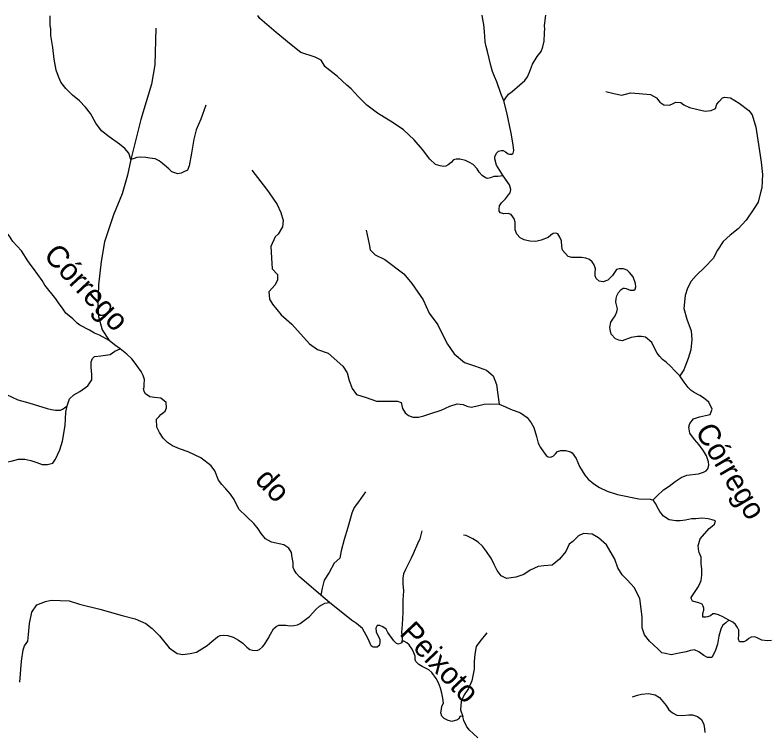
# Model space of a CAD drawing. Extents: x 436.3 to 500.4, y 8231 to 8286.4.
# Drawn here: x 461.07 to 467.97, y 8279.76 to 8286.32 of the extents above; entities that cross this region are included whole.
import ezdxf
from ezdxf.enums import TextEntityAlignment as Align

# ---------------------------------------------------------------- set-up
doc = ezdxf.new("R2010")
doc.units = 0
doc.header["$LTSCALE"] = 0.08
doc.linetypes.add('LONG_DASHED', pattern=[7.5, 6, -1.5])
doc.layers.add('61', color=7, linetype='Continuous')
doc.layers.add('7', color=7, linetype='Continuous', lineweight=25)
doc.layers.add('9', color=7, linetype='LONG_DASHED', lineweight=25)

msp = doc.modelspace()

# ---------------------------------------------------------------- linework, layer by layer
at = {"layer": '7'}
for points in [[(465.5464, 8285.5384), (465.5194, 8285.6056), (465.4833, 8285.7132), (465.4608, 8285.7625), (465.4428, 8285.8073), (465.4274, 8285.862), (465.3978, 8285.991), (465.3843, 8286.0358), (465.3752, 8286.0806), (465.3727, 8286.1274), (465.3685, 8286.1698), (465.3625, 8286.2385), (465.3536, 8286.2853), (465.3464, 8286.324)], [(465.5396, 8284.8515), (465.4782, 8284.9504), (465.463, 8285.0078), (465.463, 8285.026), (465.4781, 8285.0592), (465.4963, 8285.0773), (465.5204, 8285.0834), (465.5386, 8285.0834), (465.5598, 8285.0714), (465.5841, 8285.0533), (465.5991, 8285.0503), (465.6204, 8285.0503), (465.6322, 8285.0585), (465.6366, 8285.0854), (465.6321, 8285.1348), (465.614, 8285.2424), (465.5746, 8285.4337), (465.5464, 8285.5384)], [(467.1578, 8283.0201), (467.1083, 8283.0695), (467.0768, 8283.1055), (467.0318, 8283.1459), (467.0003, 8283.1684), (466.9733, 8283.1953), (466.9508, 8283.2268), (466.9283, 8283.2673), (466.9012, 8283.3257), (466.8427, 8283.3751), (466.8068, 8283.3795), (466.7708, 8283.3795), (466.7127, 8283.3718), (466.631, 8283.3415), (466.5977, 8283.3474), (466.5674, 8283.3595), (466.528, 8283.4018), (466.5219, 8283.4291), (466.5158, 8283.4624), (466.5248, 8283.5109), (466.543, 8283.5381), (466.5671, 8283.5684), (466.5822, 8283.6047), (466.5881, 8283.632), (466.573, 8283.6955), (466.5759, 8283.7288), (466.582, 8283.753), (466.597, 8283.7833), (466.6212, 8283.8106), (466.6394, 8283.8227), (466.6514, 8283.8228), (466.6666, 8283.8198), (466.703, 8283.8047), (466.7362, 8283.8047), (466.7484, 8283.8138), (466.7543, 8283.835), (466.7521, 8283.8652), (466.7302, 8283.9259), (466.697, 8283.9652), (466.6757, 8283.9863), (466.6424, 8283.9984), (466.6031, 8283.9983), (466.5788, 8283.9922), (466.5426, 8283.9377), (466.4972, 8283.8953), (466.4549, 8283.8801), (466.4186, 8283.8861), (466.3913, 8283.9103), (466.3822, 8283.9345), (466.3821, 8283.9677), (466.3852, 8284.001), (466.3729, 8284.0373), (466.3547, 8284.0645), (466.3305, 8284.0856), (466.2981, 8284.0982), (466.2577, 8284.1027), (466.1678, 8284.1026), (466.1364, 8284.1115), (466.0824, 8284.1698), (466.0783, 8284.2031), (466.0753, 8284.2575), (466.0601, 8284.2907), (466.0419, 8284.321), (466.0207, 8284.3269), (465.9965, 8284.3239), (465.9753, 8284.3088), (465.9512, 8284.2876), (465.8876, 8284.2633), (465.8392, 8284.2511), (465.7847, 8284.254), (465.7333, 8284.2662), (465.6969, 8284.2842), (465.6636, 8284.3175), (465.6484, 8284.3567), (465.6483, 8284.4263), (465.6392, 8284.4565), (465.627, 8284.4777), (465.6119, 8284.4988), (465.5847, 8284.5079), (465.5453, 8284.5048), (465.515, 8284.5138), (465.5029, 8284.529), (465.5029, 8284.547), (465.5069, 8284.578), (465.524, 8284.6045), (465.5602, 8284.6408), (465.5875, 8284.6772), (465.6026, 8284.6952), (465.6086, 8284.7255), (465.5964, 8284.7693), (465.5396, 8284.8515)], [(461.9308, 8283.3419), (461.8418, 8283.3924), (461.7968, 8283.4105), (461.7518, 8283.4375), (461.6619, 8283.4826), (461.6394, 8283.5006), (461.5989, 8283.5411), (461.5359, 8283.5951), (461.5044, 8283.6401), (461.4729, 8283.6806), (461.4415, 8283.726), (461.3424, 8283.8515), (461.3164, 8283.8923), (461.2389, 8284.0042), (461.2164, 8284.0312), (461.1849, 8284.0716), (461.1269, 8284.1644), (461.0499, 8284.2513), (461.0184, 8284.3006), (460.9689, 8284.359), (460.9419, 8284.3814), (460.8924, 8284.4173)], [(462.0331, 8283.2661), (461.9801, 8283.3041), (461.9308, 8283.3419)], [(463.8685, 8281.0091), (463.6742, 8281.1788), (463.6427, 8281.2103), (463.6246, 8281.2419), (463.6156, 8281.2644), (463.6156, 8281.3095), (463.6065, 8281.3546), (463.6002, 8281.4021), (463.5774, 8281.4399), (463.5319, 8281.4703), (463.4175, 8281.4945), (463.3629, 8281.5268), (463.3229, 8281.5758), (463.2959, 8281.6164), (463.2567, 8281.6672), (463.1878, 8281.7292), (463.1203, 8281.7969), (463.077, 8281.886), (463.0428, 8281.9353), (463.0012, 8281.9847), (462.9633, 8282.0227), (462.9328, 8282.0644), (462.8987, 8282.1478), (462.8645, 8282.1933), (462.7698, 8282.2692), (462.6562, 8282.3243), (462.5766, 8282.351), (462.5122, 8282.3776), (462.4667, 8282.408), (462.425, 8282.4497), (462.3909, 8282.499), (462.3682, 8282.5484), (462.3651, 8282.6214), (462.3878, 8282.6479), (462.4047, 8282.6652), (462.428, 8282.6821), (462.4432, 8282.6965), (462.4571, 8282.7247), (462.4524, 8282.7759), (462.404, 8282.8163), (462.3458, 8282.8204), (462.3033, 8282.8271), (462.2645, 8282.8533), (462.2531, 8282.876), (462.2468, 8282.906), (462.2513, 8282.9105), (462.2513, 8282.9375), (462.2558, 8282.987), (462.2422, 8283.023), (462.2242, 8283.059), (462.1612, 8283.1491), (462.1387, 8283.1761), (462.0938, 8283.2169), (462.0331, 8283.2661)], [(466.9176, 8281.8813), (466.9174, 8281.8852), (466.9488, 8281.9213), (467.0071, 8281.9754), (467.061, 8282.007), (467.1148, 8282.0521), (467.1686, 8282.0882), (467.2225, 8282.1108), (467.3303, 8282.12), (467.3752, 8282.1381), (467.3993, 8282.1502), (467.4143, 8282.1684), (467.4245, 8282.2012), (467.42, 8282.2327), (467.4019, 8282.2867), (467.3748, 8282.3317), (467.3343, 8282.3857), (467.2937, 8282.4351), (467.2487, 8282.4936), (467.2396, 8282.5476), (467.2485, 8282.5836), (467.2844, 8282.6242), (467.3383, 8282.6423), (467.3922, 8282.6559), (467.4371, 8282.6649), (467.455, 8282.7145), (467.4234, 8282.7774), (467.3739, 8282.8179), (467.3424, 8282.8403), (467.2884, 8282.8673), (467.2614, 8282.8852), (467.2344, 8282.9122), (467.1984, 8282.9617), (467.1578, 8283.0201)], [(467.6071, 8280.7804), (467.5525, 8280.8106), (467.5131, 8280.8287), (467.4827, 8280.8378), (467.4615, 8280.8377), (467.4374, 8280.8195), (467.4102, 8280.8104), (467.395, 8280.8073), (467.3677, 8280.8073), (467.3677, 8280.8406), (467.3767, 8280.8709), (467.3767, 8280.8921), (467.3705, 8280.9103), (467.3614, 8280.9284), (467.3326, 8280.9404), (467.2742, 8280.9538), (467.2652, 8280.9718), (467.2606, 8280.9898), (467.3279, 8281.089), (467.3547, 8281.1431), (467.3591, 8281.1926), (467.359, 8281.2466), (467.3544, 8281.3006), (467.3543, 8281.3591), (467.3362, 8281.3996), (467.3317, 8281.4131), (467.3271, 8281.4626), (467.345, 8281.5257), (467.4257, 8281.6204), (467.4547, 8281.6427), (467.4759, 8281.6609), (467.4855, 8281.6897), (467.4525, 8281.7015), (467.4165, 8281.7104), (467.3581, 8281.7148), (467.3042, 8281.7102), (467.2637, 8281.7102), (467.2098, 8281.6966), (467.1604, 8281.692), (467.12, 8281.6919), (467.0616, 8281.7008), (467.0076, 8281.7322), (466.976, 8281.7772), (466.9488, 8281.8192), (466.9366, 8281.8464), (466.9184, 8281.8706), (466.9176, 8281.8813)], [(464.6117, 8280.5723), (464.5815, 8280.5609), (464.5625, 8280.5684), (464.5398, 8280.5911), (464.4828, 8280.6669), (464.4677, 8280.6972), (464.4374, 8280.7199), (464.4108, 8280.7313), (464.3843, 8280.7313), (464.373, 8280.7085), (464.3768, 8280.6744), (464.3921, 8280.6403), (464.411, 8280.6063), (464.411, 8280.5721), (464.4035, 8280.5494), (464.3846, 8280.5342), (464.3505, 8280.5341), (464.3315, 8280.5455), (464.3045, 8280.6107), (464.2504, 8280.7053), (464.1964, 8280.7503), (464.1514, 8280.7819), (463.9489, 8280.944), (463.8685, 8281.0091)], [(467.998, 8280.5933), (467.9616, 8280.5901), (467.9102, 8280.5961), (467.8708, 8280.6143), (467.8435, 8280.6293), (467.8102, 8280.6263), (467.789, 8280.6142), (467.7679, 8280.5929), (467.7436, 8280.5807), (467.7194, 8280.5807), (467.7043, 8280.5837), (467.6952, 8280.6079), (467.6981, 8280.6503), (467.698, 8280.6897), (467.6859, 8280.7139), (467.6676, 8280.7412), (467.6433, 8280.7623), (467.6071, 8280.7804)], [(465.1709, 8279.8984), (465.1519, 8279.902), (465.1444, 8279.8983), (465.1369, 8279.8793), (465.1217, 8279.868), (465.0688, 8279.8527), (465.0347, 8279.8602), (465.0005, 8279.8791), (464.9778, 8279.9017), (464.9702, 8279.932), (464.974, 8279.9661), (464.9777, 8279.9926), (464.9929, 8280.0191), (464.9884, 8280.0668), (464.9794, 8280.1118), (464.9659, 8280.1567), (464.9478, 8280.2062), (464.9253, 8280.2467), (464.8856, 8280.3018), (464.8581, 8280.3264), (464.7975, 8280.3566), (464.7672, 8280.3756), (464.7406, 8280.402), (464.7331, 8280.4209), (464.733, 8280.4513), (464.7216, 8280.4815), (464.7064, 8280.5156), (464.6799, 8280.5535), (464.6572, 8280.5724), (464.6306, 8280.5874), (464.6155, 8280.5874), (464.6117, 8280.5723)], [(465.308, 8279.7031), (465.227, 8279.7749), (465.2045, 8279.8108), (465.1786, 8279.8605), (465.1709, 8279.8984)]]:
    msp.add_lwpolyline(points, dxfattribs=at)
at = {"layer": '9'}
for points in [[(462.131, 8285.0013), (462.1115, 8285.0584), (462.0748, 8285.102), (462.0257, 8285.1428), (461.9313, 8285.2081), (461.8617, 8285.2653), (461.8083, 8285.3347), (461.7591, 8285.4243), (461.714, 8285.4814), (461.6606, 8285.5385), (461.595, 8285.5914), (461.5334, 8285.6526), (461.4883, 8285.7096), (461.4678, 8285.7626), (461.4473, 8285.8196), (461.4266, 8285.9214), (461.4142, 8286.0272), (461.3978, 8286.1372), (461.3982, 8286.1641), (461.3957, 8286.2002), (461.391, 8286.2288), (461.3906, 8286.2749), (461.3895, 8286.3177)], [(465.5396, 8284.8515), (465.4914, 8284.8465), (465.4533, 8284.8464), (465.4229, 8284.8336), (465.3975, 8284.8286), (465.3772, 8284.8336), (465.3467, 8284.8564), (465.3213, 8284.8868), (465.3009, 8284.9147), (465.2653, 8284.9552), (465.2323, 8284.9754), (465.1942, 8284.9931), (465.1434, 8285.0032), (465.1103, 8285.0032), (465.085, 8284.9981), (465.0622, 8284.9752), (465.0368, 8284.9525), (465.014, 8284.9398), (464.9936, 8284.9372), (464.9632, 8284.9447), (464.9215, 8284.9564), (464.8676, 8285.0041), (464.8017, 8285.0936), (464.7238, 8285.1831), (464.628, 8285.2725), (464.5322, 8285.3381), (464.3885, 8285.4275), (464.2926, 8285.499), (464.2148, 8285.5766), (464.1489, 8285.6481), (464.107, 8285.6838), (464.0231, 8285.7613), (463.9093, 8285.8507), (463.8735, 8285.9102), (463.8195, 8285.94), (463.6878, 8285.9816), (463.598, 8286.053), (463.4603, 8286.1662), (463.3113, 8286.2931), (463.2924, 8286.3208)], [(465.5464, 8285.5384), (465.565, 8285.5666), (465.5875, 8285.6004), (465.6214, 8285.6259), (465.6919, 8285.685), (465.7371, 8285.7245), (465.7625, 8285.7583), (465.7823, 8285.8005), (465.8076, 8285.8737), (465.8499, 8285.9441), (465.8866, 8285.9919), (465.9035, 8286.0342), (465.9148, 8286.0849), (465.9161, 8286.1068), (465.9171, 8286.138), (465.9196, 8286.1717), (465.92, 8286.1915), (465.9197, 8286.2289), (465.9202, 8286.2517), (465.9243, 8286.2748), (465.9282, 8286.3024), (465.932, 8286.3249)], [(462.3595, 8286.2052), (462.3507, 8285.8693), (462.3201, 8285.6916), (462.2219, 8285.3667), (462.131, 8285.0013)], [(466.479, 8285.6257), (466.5531, 8285.6061), (466.6272, 8285.5914), (466.7063, 8285.6112), (466.7854, 8285.6064), (466.8891, 8285.5966), (466.9436, 8285.5672), (466.9733, 8285.5278), (467.0128, 8285.5032), (467.0623, 8285.4983), (467.0968, 8285.5132), (467.1215, 8285.5279), (467.166, 8285.5231), (467.1957, 8285.5034), (467.2451, 8285.4789), (467.3242, 8285.4592), (467.3884, 8285.4445), (467.4435, 8285.4494), (467.483, 8285.469), (467.4978, 8285.5085), (467.5175, 8285.5331), (467.5472, 8285.5676), (467.5669, 8285.5726), (467.6214, 8285.5677), (467.7005, 8285.5186), (467.7895, 8285.4497), (467.8192, 8285.4103), (467.8539, 8285.297), (467.8787, 8285.1393), (467.9035, 8284.9767), (467.9135, 8284.8633), (467.9088, 8284.7425), (467.8989, 8284.7129), (467.8742, 8284.6093), (467.8347, 8284.5501), (467.7656, 8284.4464), (467.6916, 8284.3674), (467.6174, 8284.3081), (467.5533, 8284.2488), (467.5039, 8284.1698), (467.4645, 8284.0957), (467.3855, 8284.0166), (467.3066, 8283.9374), (467.2621, 8283.888), (467.2276, 8283.8237), (467.208, 8283.7546), (467.1933, 8283.6359), (467.2227, 8283.5392), (467.2624, 8283.4305), (467.2676, 8283.3515), (467.2578, 8283.2576), (467.2332, 8283.1784), (467.2037, 8283.0993), (467.1939, 8283.0745), (467.1578, 8283.0201)], [(462.8172, 8285.4983), (462.7723, 8285.3718), (462.7272, 8285.2738), (462.7069, 8285.1882), (462.6856, 8285.0594), (462.6653, 8284.945), (462.6489, 8284.9042), (462.6162, 8284.8879), (462.5916, 8284.8757), (462.5588, 8284.8716), (462.5056, 8284.888), (462.4769, 8284.9166), (462.4194, 8284.9655), (462.3907, 8284.99), (462.3539, 8285.0064), (462.3046, 8285.0146), (462.2678, 8285.0187), (462.2227, 8285.0228), (462.1859, 8285.0187), (462.1612, 8285.0106), (462.131, 8285.0013)], [(462.131, 8285.0013), (462.0992, 8284.8576), (462.0501, 8284.6857), (461.9702, 8284.4955), (461.8897, 8284.2461), (461.8591, 8284.0679), (461.8347, 8283.8528), (461.8287, 8283.6621), (461.8349, 8283.5636), (461.8658, 8283.4405), (461.9308, 8283.3419)], [(463.2385, 8284.9046), (463.3716, 8284.7289), (463.3982, 8284.6958), (463.4713, 8284.5899), (463.5046, 8284.5169), (463.5246, 8284.4441), (463.518, 8284.3844), (463.4783, 8284.3181), (463.4518, 8284.2917), (463.412, 8284.2055), (463.4187, 8284.0994), (463.4255, 8283.9999), (463.472, 8283.9469), (463.4721, 8283.9004), (463.4523, 8283.854), (463.3926, 8283.7877), (463.3993, 8283.7213), (463.426, 8283.6749), (463.5059, 8283.5796), (463.6055, 8283.4933), (463.7652, 8283.3139), (463.8382, 8283.2608), (463.9378, 8283.2276), (464.0708, 8283.108), (464.1107, 8283.0482), (464.1307, 8282.9752), (464.1574, 8282.9021), (464.1973, 8282.8489), (464.2836, 8282.8224), (464.3787, 8282.7871), (464.5712, 8282.7872), (464.6044, 8282.7739), (464.6178, 8282.7207), (464.6431, 8282.6817), (464.6736, 8282.6551), (464.7117, 8282.6418), (464.763, 8282.6418), (464.8143, 8282.6533), (464.8695, 8282.6704), (464.9721, 8282.7048), (465.0519, 8282.7429), (465.1184, 8282.7639), (465.1735, 8282.7564), (465.2059, 8282.7412), (465.2478, 8282.7336), (465.3161, 8282.747), (465.3666, 8282.7606), (465.4179, 8282.7626), (465.504, 8282.7593)], [(464.2859, 8284.3539), (464.3137, 8284.226), (464.3225, 8284.1731), (464.3666, 8284.1292), (464.4548, 8284.0852), (464.6312, 8283.9532), (464.7018, 8283.8651), (464.8077, 8283.7154), (464.8608, 8283.5921), (464.9402, 8283.4864), (464.9756, 8283.4159), (465.0286, 8283.3101), (465.0904, 8283.2221), (465.1859, 8283.143), (465.2854, 8283.1073), (465.388, 8283.0701), (465.4488, 8283.0203), (465.4796, 8282.9391), (465.4885, 8282.8685), (465.504, 8282.7593)], [(461.5466, 8282.745), (461.5687, 8282.8072), (461.6078, 8282.8454), (461.6627, 8282.8774), (461.7366, 8282.9266), (461.7735, 8282.982), (461.7735, 8283.0313), (461.7672, 8283.099), (461.7672, 8283.1482), (461.7795, 8283.179), (461.798, 8283.1974), (461.8535, 8283.2035), (461.8965, 8283.2096), (461.9397, 8283.2157), (461.9828, 8283.2464), (462.0331, 8283.2661)], [(460.4177, 8283.1685), (460.4671, 8283.1254), (460.5041, 8283.0884), (460.5718, 8283.0514), (460.7383, 8282.9897), (460.8492, 8282.9464), (460.9232, 8282.9033), (460.991, 8282.8477), (461.0958, 8282.7984), (461.1944, 8282.7735), (461.3648, 8282.72), (461.4043, 8282.7108), (461.4408, 8282.7046), (461.4682, 8282.7046), (461.4864, 8282.7045), (461.5046, 8282.7136), (461.5228, 8282.7258), (461.5466, 8282.745)], [(465.504, 8282.7593), (465.561, 8282.7346), (465.6081, 8282.7133), (465.6995, 8282.6792), (465.7603, 8282.6373), (465.7966, 8282.5899), (465.8194, 8282.5461), (465.8462, 8282.4623), (465.8598, 8282.4021), (465.8827, 8282.3622), (465.9095, 8282.3222), (465.9323, 8282.2899), (465.9533, 8282.2767), (465.9741, 8282.2729), (465.9989, 8282.2824), (466.0178, 8282.3034), (466.0368, 8282.3262), (466.0672, 8282.3339), (466.1109, 8282.334), (466.1574, 8282.3243), (466.1727, 8282.313), (466.207, 8282.2617), (466.2394, 8282.1894), (466.2875, 8282.1079), (466.3185, 8282.0725), (466.3716, 8282.0284), (466.4225, 8281.9953), (466.4911, 8281.9623), (466.5884, 8281.9314), (466.7829, 8281.8919), (466.8868, 8281.8899), (466.9176, 8281.8813)], [(460.227, 8282.2696), (460.3195, 8282.1957), (460.4058, 8282.1524), (460.5537, 8282.103), (460.6153, 8282.0845), (460.6646, 8282.0844), (460.714, 8282.1028), (460.8002, 8282.1335), (460.8804, 8282.1765), (460.9666, 8282.2257), (461.0344, 8282.2379), (461.1022, 8282.2563), (461.1577, 8282.2562), (461.2131, 8282.2437), (461.2687, 8282.2252), (461.318, 8282.2066), (461.3672, 8282.2065), (461.4166, 8282.2187), (461.4412, 8282.2557), (461.4781, 8282.3418), (461.5027, 8282.4219), (461.5273, 8282.5636), (461.5334, 8282.6868), (461.5466, 8282.745)], [(464.2785, 8281.9574), (464.2134, 8281.8658), (464.1743, 8281.8135), (464.1547, 8281.7612), (464.1157, 8281.6304), (464.0832, 8281.5192), (464.0573, 8281.4146), (464.0443, 8281.3492), (463.9922, 8281.3034), (463.9465, 8281.2184), (463.901, 8281.1465), (463.8815, 8281.0745), (463.8685, 8281.0091)], [(464.795, 8281.5979), (464.7756, 8281.5259), (464.7561, 8281.4801), (464.717, 8281.3885), (464.6975, 8281.3493), (464.6454, 8281.2446), (464.6259, 8281.2054), (464.6195, 8281.1661), (464.6196, 8281.1138), (464.6262, 8281.0484), (464.6198, 8280.9635), (464.62, 8280.8522), (464.6136, 8280.7411), (464.6072, 8280.6692), (464.6137, 8280.6234), (464.6117, 8280.5723)], [(465.6568, 8281.1743), (465.5717, 8281.1624), (465.5223, 8281.1856), (465.4852, 8281.2358), (465.4563, 8281.2899), (465.4316, 8281.344), (465.3863, 8281.4097), (465.3492, 8281.4599), (465.3121, 8281.4947), (465.2627, 8281.5256), (465.2009, 8281.5565), (465.1762, 8281.5603)], [(467.6071, 8280.7804), (467.5802, 8280.7575), (467.5476, 8280.7314), (467.5346, 8280.6987), (467.5151, 8280.6333), (467.5023, 8280.5615), (467.4827, 8280.4962), (467.4503, 8280.4374), (467.411, 8280.4373), (467.3784, 8280.4568), (467.3327, 8280.4894), (467.2934, 8280.5089), (467.2542, 8280.5023), (467.2151, 8280.4892), (467.1368, 8280.4759), (467.0781, 8280.4628), (467.0258, 8280.4757), (466.9932, 8280.4822), (466.9579, 8280.5162), (466.8795, 8280.5879), (466.8337, 8280.6466), (466.814, 8280.7119), (466.8138, 8280.8098), (466.7929, 8280.9806), (466.7405, 8281.0786), (466.675, 8281.1503), (466.6293, 8281.1959), (466.59, 8281.2611), (466.5637, 8281.3395), (466.4851, 8281.4701), (466.4132, 8281.5353), (466.3544, 8281.5678), (466.2761, 8281.5741), (466.2305, 8281.5545), (466.1784, 8281.5021), (466.1458, 8281.4759), (466.1132, 8281.4105), (466.0547, 8281.3385), (465.9895, 8281.286), (465.9111, 8281.2794), (465.8589, 8281.2728), (465.7872, 8281.2399), (465.7285, 8281.2005), (465.6568, 8281.1743)], [(461.1126, 8280.2127), (461.1275, 8280.4046), (461.1423, 8280.5079), (461.1571, 8280.5448), (461.1866, 8280.5891), (461.194, 8280.6481), (461.2014, 8280.7515), (461.2236, 8280.8548), (461.268, 8280.9213), (461.3493, 8280.9506), (461.4011, 8280.9653), (461.5637, 8280.9575), (461.6599, 8280.9278), (461.8447, 8280.883), (462.0518, 8280.8233), (462.1701, 8280.7934), (462.2662, 8280.7488), (462.3254, 8280.7044), (462.392, 8280.6378), (462.4807, 8280.5267), (462.5548, 8280.4748), (462.6065, 8280.4672), (462.6731, 8280.4745), (462.7322, 8280.489), (462.8283, 8280.5479), (462.8726, 8280.5848), (462.9244, 8280.629), (462.9489, 8280.6398), (462.9787, 8280.6434), (463.0179, 8280.6396), (463.0663, 8280.6246), (463.1166, 8280.5984), (463.1557, 8280.5685), (463.1931, 8280.5348), (463.221, 8280.5125), (463.2434, 8280.505), (463.2825, 8280.503), (463.3086, 8280.5105), (463.3366, 8280.5364), (463.3543, 8280.5588), (463.3878, 8280.6127), (463.4101, 8280.6518), (463.4362, 8280.7021), (463.4603, 8280.7225), (463.4864, 8280.7336), (463.5125, 8280.7355), (463.5479, 8280.7335), (463.587, 8280.7279), (463.6224, 8280.7315), (463.6559, 8280.7371), (463.6801, 8280.7501), (463.7675, 8280.8152), (463.8252, 8280.8786), (463.8586, 8280.9083), (463.8847, 8280.9232), (463.9071, 8280.9362), (463.9489, 8280.944)], [(465.3907, 8280.6639), (465.3255, 8280.5854), (465.2929, 8280.5396), (465.28, 8280.4677), (465.2735, 8280.4024), (465.2736, 8280.3306), (465.2542, 8280.226), (465.2216, 8280.154), (465.1826, 8280.0953), (465.1565, 8280.0364), (465.1501, 8279.958), (465.1709, 8279.8984)], [(466.7248, 8280.0784), (466.7709, 8280.095), (466.8072, 8280.1016), (466.8699, 8280.1083), (466.9028, 8280.1019), (466.9325, 8280.0953), (466.9722, 8280.0723), (467.0019, 8280.0361), (467.0316, 8279.9999), (467.058, 8279.9603), (467.091, 8279.9307), (467.1307, 8279.911), (467.1834, 8279.9078), (467.2396, 8279.9145), (467.2725, 8279.9146), (467.3187, 8279.8982), (467.355, 8279.8719), (467.3782, 8279.8258), (467.3849, 8279.7862), (467.3882, 8279.75)]]:
    msp.add_lwpolyline(points, dxfattribs=at)

# ---------------------------------------------------------------- texts
at = {"layer": '61'}
for s, rotation, p in [('Córrego                         do                      Peixoto', 313.288, (463.2576, 8282.059)), ('Córrego           Verde', 300.627, (467.9292, 8281.4382))]:
    msp.add_text(s, height=0.2, rotation=rotation, dxfattribs=at).set_placement(p, align=Align.CENTER)

doc.saveas('drawing.dxf')
